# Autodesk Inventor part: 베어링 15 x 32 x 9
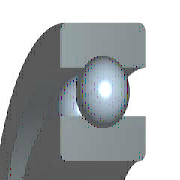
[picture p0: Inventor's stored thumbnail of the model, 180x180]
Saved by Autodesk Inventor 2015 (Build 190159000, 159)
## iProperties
IsCustomPart: 0
Created: 2012-02
Part Number: 베어링 15 x 32 x 9
Material: 강철, 연강
Description: 깊은 그루브 볼 베어링
Document SubType Name: Modeling
Standard: KS B 2023
Designer: mduedu
Standards Organization: KS
Language: ko-KR
Size Designation: 6002 - 15 x 32 x 9
Categories: <MemberInstance><Categories><Category DisplayName="샤프트 부품" InternalName="7f7aeb1f-a693-4053-b835-cee3144e0d98" Mnemonic="SHFT"><Category DisplayName="베어링" Inter
Density: 1 g/cm^3
Appearance: 강철
Author: mduedu
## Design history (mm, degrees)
sketch "스케치" dims "d0" = 4.42 (= -0.26 x WD + 0.26 x BD)
  geometry: L1 (2.29, 11.75)-(6.71, 11.75); L2 (4.5, 11.75)-(4.5, 9.54); L3 (4.5, 11.75)-(4.5, 13.96); L4 (2.858, 10.271)-(0, 10.271); L5 (0, 7.5)-(9, 7.5); L6 (2.858, 13.229)-(0, 13.229); L7 (0, 16)-(9, 16); L8 (9, 7.5)-(9, 10.271); L9 (6.142, 10.271)-(9, 10.271); L10 (6.142, 13.229)-(9, 13.229); L11 (9, 16)-(9, 13.229); L12 (-1.4, 0)-(8.4, 0) reference; L13 (0, -0.3)-(0, 5.3) reference
  constraints: 22 end point, 4 point on line, 2 collinear, 2 perpendicular, 2 symmetric about line, 1 midpoint, 1 parallel, 14 other
  dimensions: "d9" = 15 diameter of L5 L12 (= WD); "d11" = 32 diameter of L7 L12 (= BD); "d12" = 9 distance between parallel lines of L8 L13 (= KB); "d13" = 20.542 diameter of L9 L12 (= 0.326 x BD + 0.674 x WD)
revolve "본체" stored, may be unused: angle "d6" = 90 deg
revolve "볼" stored, may be unused: angle "d7" = 90 deg
pattern_circular "IDS_ARRAYBALL[SIMPL:T]" dims angle "d3" = 360 deg
body "Solid1"
fillet "모깎기1" dims "d1" = 0.3 (= KRS)
other parameters: "WD" = 15 [user parameter; used in 5 equation terms], "BD" = 32 [user parameter; used in 5 equation terms], "KB" = 9 [user parameter; used in 1 equation term], "KRS" = 0.3 [user parameter; used in 1 equation term], "d4" = 0, "d5" = 0, "d8" = 0, "d14" = 0, "d15" = 0, "BBA" = 0 [user parameter], "BC0" = 2850000 [user parameter], "BC" = 5590000 [user parameter], "BR" = 16 (= 0.5 x BD) [user parameter], "WR" = 7.5 (= 0.5 x WD) [user parameter]
